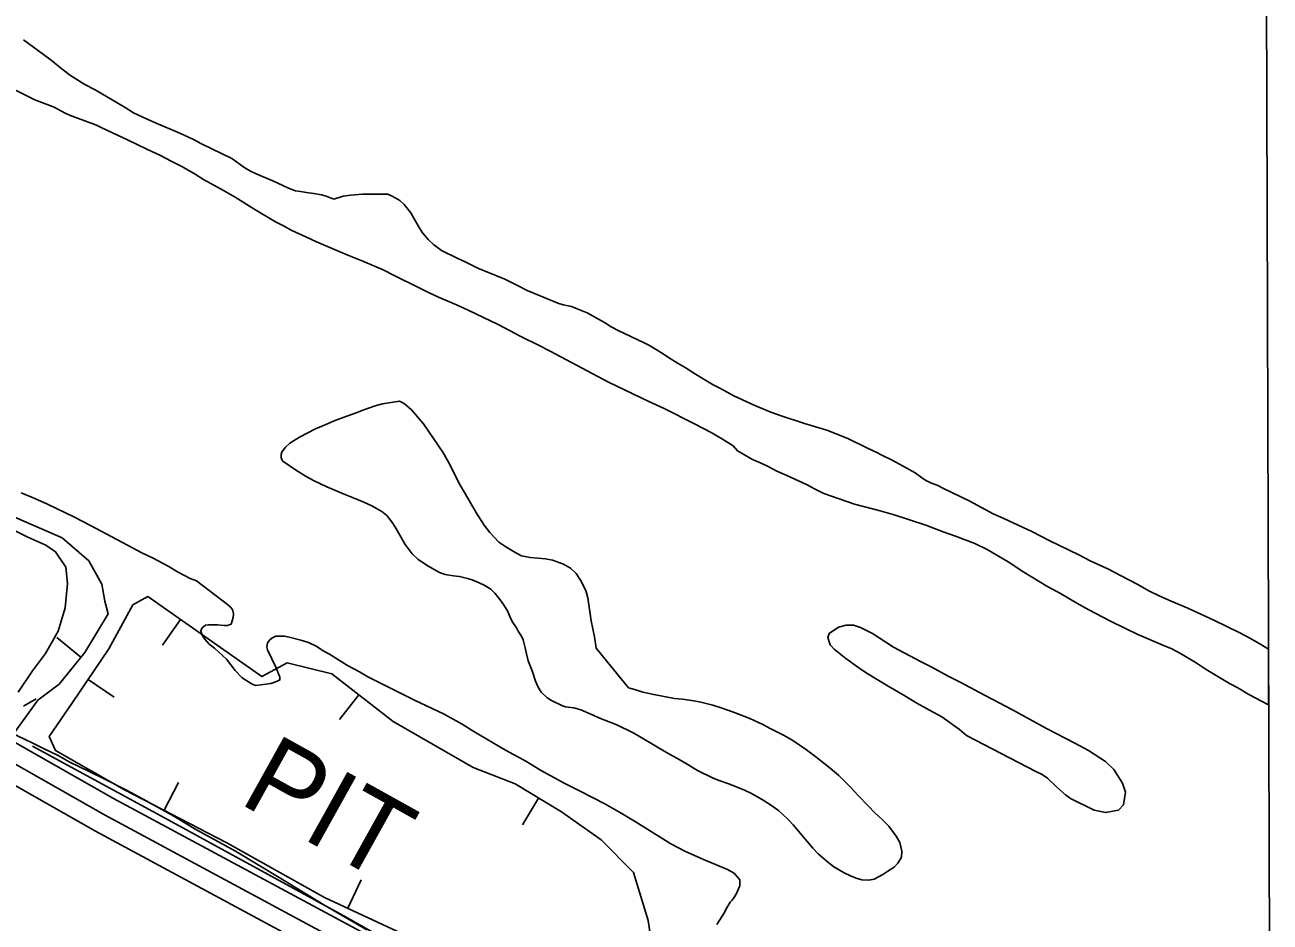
# Model space of a CAD drawing. Extents: x 3355724 to 3393621, y 594744 to 620174.
# Drawn here: x 3390457 to 3391453, y 600421 to 601139 of the extents above; entities that cross this region are included whole.
import ezdxf

# ---------------------------------------------------------------- set-up
doc = ezdxf.new("R2010")
doc.units = 0
for name, color, linetype in [('V-BORW-IDEN', 7, 'Continuous'), ('V-BORW-LINE', 7, 'Continuous'), ('V-GRID-FRAM', 7, 'Continuous'), ('V-ROAD-CNTR', 7, 'Continuous'), ('V-SITE-VEGE', 7, 'Continuous'), ('V-TOPO-SHOR', 7, 'Continuous')]:
    doc.layers.add(name, color=color, linetype=linetype)

msp = doc.modelspace()

# ---------------------------------------------------------------- linework, layer by layer
at = {"layer": 'V-BORW-LINE'}
for p, q in [((3390581.16, 600662.84), (3390566.81, 600642.36)), ((3390501.58, 600632.72), (3390482.21, 600648.53)), ((3390507.31, 600614.81), (3390528.02, 600600.81)), ((3390723.83, 600602.64), (3390708.48, 600582.91)), ((3390568.05, 600510.3), (3390579.58, 600532.48)), ((3390867.64, 600520.02), (3390854.68, 600498.64)), ((3390714.99, 600431.89), (3390725.56, 600454.54))]:
    msp.add_line(p, q, dxfattribs=at)
for points in [[(3390404.04, 600763.89), (3390486.52, 600728.08), (3390507.98, 600709.75), (3390518.18, 600691.2), (3390520.68, 600677.53), (3390523.21, 600667.3), (3390504.57, 600636.39), (3390484.04, 600611.21), (3390467.07, 600598.22), (3390447.03, 600570.55)], [(3390792.72, 600395.6), (3390696.46, 600440.54), (3390618.13, 600484.24), (3390536.51, 600526.7), (3390481.14, 600558.15), (3390476.13, 600569.17), (3390494.88, 600596.42), (3390523.86, 600639.31), (3390543.04, 600674.49), (3390554.93, 600681.22)], [(3390554.93, 600681.22), (3390646.3, 600617.19), (3390666.61, 600628.08), (3390702.33, 600619.37), (3390751.34, 600581.23), (3390815.26, 600544.46), (3390848.81, 600531.43), (3390885.84, 600508.99), (3390917.59, 600486.64), (3390943.54, 600460.38), (3390955.36, 600422.12), (3390964.29, 600360.67)], [(3390465.81, 600599.35), (3390455.56, 600593.54)]]:
    msp.add_lwpolyline(points, dxfattribs=at)
at = {"layer": 'V-GRID-FRAM'}
msp.add_lwpolyline([(3359807.56, 618312.07), (3391397.17, 618394.77), (3391452.71, 600211.22), (3359847.23, 600128.47), (3359807.56, 618312.07)], dxfattribs=at)
at = {"layer": 'V-ROAD-CNTR'}
for points in [[(3388228.72, 601693.23), (3388290.02, 601667.91), (3388382.76, 601630.25), (3388484.12, 601588.91), (3388574.06, 601563.02), (3388632.6, 601540.78), (3388725.29, 601494.91), (3388815.98, 601448.79), (3388916.72, 601401.26), (3389012.52, 601354.23), (3389189.03, 601262.02), (3389389.7, 601151.38), (3389619.09, 601026.75), (3389753.93, 600954.59), (3390006.73, 600812.22), (3390248.96, 600678.1), (3390527.61, 600519.78), (3390796.25, 600375.08), (3390931.22, 600305.52), (3391018, 600247.9), (3391053.94, 600226.08)], [(3388223, 601679.37), (3388284.34, 601654.03), (3388377.11, 601616.35), (3388479.2, 601574.72), (3388569.32, 601548.78), (3388626.59, 601527.02), (3388718.57, 601481.5), (3388809.38, 601435.32), (3388910.21, 601387.74), (3389005.74, 601340.84), (3389181.94, 601248.8), (3389382.49, 601138.23), (3389611.97, 601013.54), (3389746.71, 600941.44), (3389999.42, 600799.12), (3390241.62, 600665.02), (3390520.35, 600506.65), (3390789.26, 600361.81), (3390923.61, 600292.57), (3391009.95, 600235.24), (3391046.15, 600213.25)], [(3388217.27, 601665.5), (3388278.65, 601640.15), (3388371.45, 601602.46), (3388474.28, 601560.52), (3388564.57, 601534.53), (3388620.59, 601513.25), (3388711.84, 601468.09), (3388802.77, 601421.85), (3388903.71, 601374.22), (3388998.96, 601327.46), (3389174.84, 601235.59), (3389375.29, 601125.07), (3389604.85, 601000.34), (3389739.49, 600928.29), (3389992.1, 600786.03), (3390234.28, 600651.94), (3390513.08, 600493.52), (3390782.26, 600348.54), (3390916, 600279.61), (3391001.91, 600222.57), (3391038.36, 600200.43)]]:
    msp.add_lwpolyline(points, dxfattribs=at)
at = {"layer": 'V-SITE-VEGE'}
for p, q in [((3390455.7, 601126.52), (3390471.71, 601114.96)), ((3390471.71, 601114.96), (3390477.71, 601110.45)), ((3390477.71, 601110.45), (3390486.62, 601103.04)), ((3390486.62, 601103.04), (3390493.17, 601098.16)), ((3390464.75, 601078.65), (3390439.67, 601091.09)), ((3390493.17, 601098.16), (3390504.62, 601090.94)), ((3390504.62, 601090.94), (3390512.8, 601086.61)), ((3390512.8, 601086.61), (3390536.97, 601072.36)), ((3390480.01, 601072.72), (3390464.75, 601078.65)), ((3390488.37, 601068.21), (3390480.01, 601072.72)), ((3390536.97, 601072.36), (3390543.7, 601068.21)), ((3390492.36, 601066.41), (3390488.37, 601068.21)), ((3390504.53, 601061.73), (3390492.36, 601066.41)), ((3390513.98, 601058.31), (3390504.53, 601061.73)), ((3390543.7, 601068.21), (3390554.42, 601063.16)), ((3390554.42, 601063.16), (3390561.69, 601059.92)), ((3390561.69, 601059.92), (3390580.58, 601052)), ((3390518.71, 601055.97), (3390513.98, 601058.31)), ((3390538.87, 601046.6), (3390518.71, 601055.97)), ((3390580.58, 601052), (3390591.48, 601046.77)), ((3390554.86, 601038.85), (3390538.87, 601046.6)), ((3390591.48, 601046.77), (3390598.02, 601043.35)), ((3390598.02, 601043.35), (3390622.19, 601031.63)), ((3390564.67, 601034.35), (3390554.86, 601038.85)), ((3390573.58, 601029.66), (3390564.67, 601034.35)), ((3390582.12, 601025.33), (3390573.58, 601029.66)), ((3390622.19, 601031.63), (3390632.74, 601024.23)), ((3390592.84, 601019.02), (3390582.12, 601025.33)), ((3390632.74, 601024.23), (3390637.1, 601021.52)), ((3390637.1, 601021.52), (3390641.83, 601019.36)), ((3390641.83, 601019.36), (3390654.91, 601013.78)), ((3390599.57, 601014.87), (3390592.84, 601019.02)), ((3390615.56, 601006.03), (3390599.57, 601014.87)), ((3390654.91, 601013.78), (3390662.9, 601010.17)), ((3390662.9, 601010.17), (3390667.44, 601008.02)), ((3390625.02, 601000.62), (3390615.56, 601006.03)), ((3390640.65, 600990.87), (3390625.02, 601000.62)), ((3390667.44, 601008.02), (3390673.07, 601005.86)), ((3390673.07, 601005.86), (3390677.25, 601005.32)), ((3390677.25, 601005.32), (3390683.6, 601004.26)), ((3390683.6, 601004.26), (3390687.78, 601003.73)), ((3390687.78, 601003.73), (3390693.95, 601002.48)), ((3390693.95, 601002.48), (3390697.58, 601001.58)), ((3390697.58, 601001.58), (3390701.58, 600999.96)), ((3390701.58, 600999.96), (3390703.75, 600999.24)), ((3390703.75, 600999.24), (3390711.37, 601001.44)), ((3390711.37, 601001.44), (3390717.35, 601002.37)), ((3390717.35, 601002.37), (3390726.78, 601003.13)), ((3390726.78, 601003.13), (3390743.84, 601003.18)), ((3390743.84, 601003.18), (3390747.1, 601003.01)), ((3390747.1, 601003.01), (3390750.92, 601001.39)), ((3390750.92, 601001.39), (3390756.73, 600998.14)), ((3390657.19, 600980.95), (3390640.65, 600990.87)), ((3390756.73, 600998.14), (3390760.19, 600994.89)), ((3390760.19, 600994.89), (3390765.48, 600988.19)), ((3390663.55, 600977.7), (3390657.19, 600980.95)), ((3390765.48, 600988.19), (3390768.21, 600983.48)), ((3390768.21, 600983.48), (3390772.04, 600976.42)), ((3390670.27, 600974.1), (3390663.55, 600977.7)), ((3390681.54, 600969.05), (3390670.27, 600974.1)), ((3390772.04, 600976.42), (3390774.78, 600972.26)), ((3390774.78, 600972.26), (3390779.51, 600966.47)), ((3390690.08, 600965.09), (3390681.54, 600969.05)), ((3390704.43, 600958.79), (3390690.08, 600965.09)), ((3390779.51, 600966.47), (3390783.52, 600962.85)), ((3390783.52, 600962.85), (3390790.06, 600958.16)), ((3390715.15, 600954.28), (3390704.43, 600958.79)), ((3390726.96, 600949.61), (3390715.15, 600954.28)), ((3390743.31, 600942.58), (3390726.96, 600949.61)), ((3390790.06, 600958.16), (3390802.97, 600951.67)), ((3390802.97, 600951.67), (3390808.96, 600948.97)), ((3390752.21, 600938.08), (3390743.31, 600942.58)), ((3390808.96, 600948.97), (3390818.96, 600943.92)), ((3390818.96, 600943.92), (3390822.23, 600942.48)), ((3390822.23, 600942.48), (3390833.31, 600938.16)), ((3390754.76, 600936.63), (3390752.21, 600938.08)), ((3390768.93, 600929.79), (3390754.76, 600936.63)), ((3390779.47, 600924.56), (3390768.93, 600929.79)), ((3390833.31, 600938.16), (3390840.57, 600935.1)), ((3390840.57, 600935.1), (3390851.29, 600929.87)), ((3390851.29, 600929.87), (3390858.56, 600926.09)), ((3390787.65, 600920.78), (3390779.47, 600924.56)), ((3390801.82, 600914.65), (3390787.65, 600920.78)), ((3390858.56, 600926.09), (3390868.73, 600921.77)), ((3390868.73, 600921.77), (3390883.09, 600916.01)), ((3390811.26, 600910.33), (3390801.82, 600914.65)), ((3390835.25, 600898.98), (3390811.26, 600910.33)), ((3390883.09, 600916.01), (3390887.27, 600914.57)), ((3390887.27, 600914.57), (3390893.98, 600913.14)), ((3390893.98, 600913.14), (3390898.52, 600911.52)), ((3390898.52, 600911.52), (3390906.33, 600908.1)), ((3390906.33, 600908.1), (3390920.33, 600900.34)), ((3390920.33, 600900.34), (3390925.78, 600897.1)), ((3390848.88, 600891.59), (3390835.25, 600898.98)), ((3390853.42, 600889.24), (3390848.88, 600891.59)), ((3390925.78, 600897.1), (3390931.24, 600894.03)), ((3390931.24, 600894.03), (3390951.95, 600884.3)), ((3390867.41, 600882.39), (3390853.42, 600889.24)), ((3390876.86, 600877.53), (3390867.41, 600882.39)), ((3390951.95, 600884.3), (3390956.31, 600881.96)), ((3390956.31, 600881.96), (3390961.04, 600879.25)), ((3390923.57, 600852.82), (3390876.86, 600877.53)), ((3390961.04, 600879.25), (3390967.22, 600875.46)), ((3390967.22, 600875.46), (3390971.58, 600872.39)), ((3390971.58, 600872.39), (3390979.22, 600867.7)), ((3390979.22, 600867.7), (3390984.85, 600864.45)), ((3390984.85, 600864.45), (3390993.21, 600859.04)), ((3390955.91, 600837.14), (3390923.57, 600852.82)), ((3390993.21, 600859.04), (3391007.21, 600850.55)), ((3391007.21, 600850.55), (3391013.21, 600847.67)), ((3391013.21, 600847.67), (3391023.75, 600841.9)), ((3391023.75, 600841.9), (3391040.64, 600834.15)), ((3390968.09, 600831.56), (3390955.91, 600837.14)), ((3390992.25, 600819.3), (3390968.09, 600831.56)), ((3391040.64, 600834.15), (3391053.36, 600828.75)), ((3391053.36, 600828.75), (3391061.72, 600825.69)), ((3391061.72, 600825.69), (3391080.24, 600819.59)), ((3391005.52, 600812.45), (3390992.25, 600819.3)), ((3391014.79, 600807.22), (3391005.52, 600812.45)), ((3391080.24, 600819.59), (3391090.96, 600816.54)), ((3391090.96, 600816.54), (3391098.04, 600814.2)), ((3391098.04, 600814.2), (3391114.93, 600807.54)), ((3391023.15, 600801.8), (3391014.79, 600807.22)), ((3391026.79, 600797.82), (3391023.15, 600801.8)), ((3391114.93, 600807.54), (3391130.02, 600800.15)), ((3391030.43, 600795.66), (3391026.79, 600797.82)), ((3391038.79, 600790.97), (3391030.43, 600795.66)), ((3391045.51, 600787.91), (3391038.79, 600790.97)), ((3391130.02, 600800.15), (3391138.73, 600796.19)), ((3391138.73, 600796.19), (3391141.64, 600794.57)), ((3391141.64, 600794.57), (3391150.37, 600790.24)), ((3391150.37, 600790.24), (3391164, 600782.85)), ((3391051.14, 600785.2), (3391045.51, 600787.91)), ((3391058.23, 600781.6), (3391051.14, 600785.2)), ((3391066.05, 600777.99), (3391058.23, 600781.6)), ((3391164, 600782.85), (3391168.72, 600780.14)), ((3391081.85, 600770.97), (3391066.05, 600777.99)), ((3391088.39, 600767.36), (3391081.85, 600770.97)), ((3391168.72, 600780.14), (3391174, 600776.35)), ((3391174, 600776.35), (3391177.45, 600774.18)), ((3391177.45, 600774.18), (3391183.08, 600771.48)), ((3391183.08, 600771.48), (3391186.35, 600770.22)), ((3391095.84, 600763.76), (3391088.39, 600767.36)), ((3391108.01, 600759.26), (3391095.84, 600763.76)), ((3391186.35, 600770.22), (3391191.44, 600767.7)), ((3391191.44, 600767.7), (3391212.52, 600757.61)), ((3391120.37, 600755.13), (3391108.01, 600759.26)), ((3391140.88, 600749.75), (3391120.37, 600755.13)), ((3391212.52, 600757.61), (3391231.24, 600747.51)), ((3391151.96, 600746.71), (3391140.88, 600749.75)), ((3391177.38, 600738.44), (3391151.96, 600746.71)), ((3391231.24, 600747.51), (3391239.77, 600743.73)), ((3391239.77, 600743.73), (3391262.67, 600733.1)), ((3391191.19, 600733.05), (3391177.38, 600738.44)), ((3391201.18, 600729.45), (3391191.19, 600733.05)), ((3391262.67, 600733.1), (3391276.48, 600725.89)), ((3391216.62, 600723.69), (3391201.18, 600729.45)), ((3391226.43, 600718.83), (3391216.62, 600723.69)), ((3391276.48, 600725.89), (3391299.74, 600714.53)), ((3391243.16, 600709.09), (3391226.43, 600718.83)), ((3391299.74, 600714.53), (3391308.83, 600709.84)), ((3391255.7, 600700.6), (3391243.16, 600709.09)), ((3391274.24, 600689.59), (3391255.7, 600700.6)), ((3391308.83, 600709.84), (3391323.36, 600702.99)), ((3391323.36, 600702.99), (3391332.99, 600698.13)), ((3391332.99, 600698.13), (3391346.99, 600690.74)), ((3391346.99, 600690.74), (3391355.71, 600685.87)), ((3391284.96, 600683.64), (3391274.24, 600689.59)), ((3391298.05, 600675.88), (3391284.96, 600683.64)), ((3391355.71, 600685.87), (3391364.61, 600681.54)), ((3391364.61, 600681.54), (3391373.7, 600677.4)), ((3391307.69, 600670.47), (3391298.05, 600675.88)), ((3391373.7, 600677.4), (3391386.78, 600671.82)), ((3391386.78, 600671.82), (3391407.67, 600662.45)), ((3391324.58, 600661.82), (3391307.69, 600670.47)), ((3391337.67, 600655.51), (3391324.58, 600661.82)), ((3391407.67, 600662.45), (3391428.39, 600652.18)), ((3391346.39, 600651.18), (3391337.67, 600655.51)), ((3391366.92, 600642.36), (3391346.39, 600651.18)), ((3391428.39, 600652.18), (3391436.39, 600647.85)), ((3391374.18, 600639.48), (3391366.92, 600642.36)), ((3391436.39, 600647.85), (3391444.38, 600643.34)), ((3391444.38, 600643.34), (3391451.4, 600639.22)), ((3391381.09, 600635.69), (3391374.18, 600639.48)), ((3391393.45, 600628.3), (3391381.09, 600635.69)), ((3391451.4, 600639.22), (3391451.54, 600594.51)), ((3391401.63, 600622.88), (3391393.45, 600628.3)), ((3391420.17, 600611.69), (3391401.63, 600622.88)), ((3391426.9, 600608.08), (3391420.17, 600611.69)), ((3391435.8, 600602.85), (3391426.9, 600608.08)), ((3391451.54, 600594.51), (3391435.8, 600602.85))]:
    msp.add_line(p, q, dxfattribs=at)
for points in [[(3390986.43, 600547.15), (3390980.06, 600550.94), (3390969.89, 600556.35), (3390951.53, 600567.36), (3390943.71, 600571.87), (3390930.08, 600578.53), (3390915.73, 600584.11), (3390911.19, 600586.28), (3390901.38, 600590.6), (3390895.75, 600592.21), (3390889.21, 600593.1), (3390886.67, 600593.82), (3390877.95, 600598.14), (3390874.32, 600600.49), (3390869.77, 600604.83), (3390867.21, 600608.81), (3390865.02, 600613.52), (3390862.45, 600621.86), (3390859.35, 600629.83), (3390858.06, 600635.27), (3390856.77, 600640.16), (3390855.3, 600646.51), (3390854.02, 600649.41), (3390851.28, 600653.39), (3390849.82, 600656.29), (3390846.54, 600661.36), (3390844.71, 600665.16), (3390842.89, 600669.33), (3390839.42, 600674.76), (3390836.87, 600678.56), (3390832.5, 600683.99), (3390829.41, 600687.06), (3390824.13, 600690.31), (3390820.13, 600692.29), (3390814.5, 600694.63), (3390810.69, 600695.71), (3390804.34, 600697.14), (3390799.62, 600697.67), (3390792.9, 600698.92), (3390788.36, 600700.53), (3390778.54, 600706.13), (3390771.09, 600711.18), (3390766.54, 600715.34), (3390760.89, 600722.94), (3390753.41, 600735.98), (3390750.68, 600740.14), (3390746.3, 600745.94), (3390742.3, 600749.37), (3390734.12, 600753.7), (3390727.95, 600756.76), (3390718.68, 600760.54), (3390711.96, 600763.06), (3390705.24, 600765.94), (3390698.33, 600769), (3390687.98, 600773.87), (3390681.62, 600777.3), (3390673.07, 600782.53), (3390663.07, 600789.57), (3390661.61, 600791.92), (3390661.6, 600794.83), (3390662.32, 600796.82), (3390665.21, 600800.82), (3390668.65, 600803.92), (3390676.43, 600808.84), (3390689.11, 600815.41), (3390695.63, 600817.98), (3390705.42, 600822.36), (3390721.73, 600828.22), (3390727.89, 600830.6), (3390736.95, 600833.71), (3390742.75, 600835.36), (3390751.27, 600836.84), (3390756.35, 600837.4), (3390759.98, 600835.6), (3390765.99, 600830.54), (3390775.46, 600819.32), (3390790.95, 600796.7), (3390796.61, 600786.74), (3390804.09, 600771.7), (3390809.02, 600763.01), (3390816.13, 600751.24), (3390817.96, 600747.8), (3390823.98, 600738.39), (3390828.53, 600732.42), (3390835.81, 600724.82), (3390841.27, 600721.03), (3390849.45, 600716.15), (3390853.99, 600713.81), (3390860.89, 600712.38), (3390873.05, 600711.51), (3390878.68, 600710.26), (3390887.58, 600707.03), (3390893.03, 600703.96), (3390897.76, 600699.62), (3390901.23, 600694.19), (3390905.42, 600686.04), (3390907.08, 600680.06), (3390909.68, 600661.92), (3390912.25, 600648.87), (3390913.56, 600639.8), (3390939.42, 600608.14)], [(3390453.62, 600764.3), (3390464.7, 600759.61), (3390474.88, 600755.11), (3390496.32, 600744.66), (3390509.22, 600738.17), (3390530.31, 600726.81), (3390550.84, 600715.99), (3390559.2, 600712.03), (3390571.37, 600705.54), (3390578.83, 600701.02), (3390588.82, 600695.61), (3390593.91, 600693.82)], [(3390593.91, 600693.82), (3390618.64, 600674.85), (3390620.83, 600672.86), (3390622.65, 600670.87), (3390623.56, 600667.42), (3390623.4, 600664.34), (3390621.6, 600659.25), (3390618.7, 600657.97), (3390615.98, 600657.97), (3390611.08, 600658.49), (3390607.99, 600658.67), (3390603.64, 600658.65), (3390601.1, 600658.28), (3390598.21, 600655.91), (3390597.49, 600653.55), (3390598.77, 600649.74), (3390600.59, 600647.21), (3390604.23, 600643.05), (3390608.42, 600639.8), (3390617.88, 600631.12), (3390624.98, 600622.08), (3390630.44, 600616.29), (3390638.44, 600611.05), (3390641.35, 600610.15), (3390653.32, 600611.64), (3390657.85, 600613.29), (3390660.75, 600614.57), (3390660.56, 600616.75), (3390657.63, 600624.17), (3390650.87, 600638.67), (3390650.32, 600640.66), (3390650.67, 600644.29), (3390652.66, 600646.47), (3390654.29, 600647.93), (3390657.37, 600649.39), (3390659.54, 600649.58), (3390664.26, 600649.41), (3390668.08, 600648.7), (3390677.52, 600646.37), (3390683.69, 600644.4), (3390690.23, 600641.33), (3390695.32, 600637.9), (3390700.41, 600635.2), (3390714.77, 600626.18), (3390724.4, 600620.94), (3390730.95, 600616.97), (3390764.02, 600600.39), (3390768.38, 600598.41), (3390792, 600587.06), (3390806.36, 600579.12), (3390815.81, 600573.17), (3390841.08, 600558.37), (3390857.44, 600549.54), (3390869.25, 600542.32), (3390888.15, 600531.85), (3390900.87, 600525.55), (3390920.68, 600515.27), (3390933.59, 600507.87), (3390945.59, 600500.83), (3390973.4, 600483.33), (3390984.48, 600477.56), (3390999.38, 600470.9), (3391018.82, 600462.79), (3391024.09, 600459.91), (3391028.46, 600454.66), (3391028.48, 600449.76), (3391025.6, 600443.04), (3391023.79, 600440.13), (3391022.35, 600438.31), (3391020.72, 600436.68), (3391017.47, 600430.86), (3391016.21, 600428.32), (3391010.07, 600418.86)], [(3390939.42, 600608.14), (3390945.41, 600606.52), (3390950.86, 600604.73), (3390959.76, 600602.76), (3390976.28, 600599.73), (3390982.63, 600599.03), (3390991.7, 600597.79), (3390997.33, 600596.71), (3391006.95, 600594.39), (3391013.67, 600592.23), (3391023.48, 600588.82), (3391036.56, 600583.6), (3391046.92, 600578.73), (3391053.46, 600575.31), (3391064, 600570.08), (3391071.09, 600566.11), (3391082, 600558.53), (3391089.45, 600552.93), (3391100.91, 600543.9), (3391107.83, 600538.11), (3391117.29, 600528.53), (3391122.94, 600522.2), (3391131.31, 600513.7), (3391136.59, 600508.09), (3391142.23, 600503.03), (3391147.69, 600497.6), (3391153.7, 600489.46), (3391156.44, 600484.39), (3391158.09, 600477.5), (3391157.75, 600472.78), (3391155.04, 600467.87), (3391151.96, 600464.78), (3391147.08, 600461.5), (3391142.91, 600458.94), (3391136.03, 600455.11), (3391131.86, 600454.19), (3391126.06, 600454.53), (3391121.7, 600455.79), (3391116.98, 600457.77), (3391111.89, 600460.3), (3391103.71, 600464.98), (3391098.62, 600468.96), (3391091.34, 600475.47), (3391086.97, 600479.81), (3391071.31, 600498.62), (3391066.57, 600503.33), (3391059.66, 600509.65), (3391054.75, 600513.45), (3391047.11, 600518.32), (3391042.21, 600521.21), (3391037.3, 600523.91), (3391032.39, 600526.26), (3391019.86, 600531.3), (3391012.05, 600533.99), (3391007.14, 600535.97), (3390994.6, 600542.1), (3390986.43, 600547.15)], [(3390659.99, 600456.55), (3390625.09, 600477.48), (3390605.82, 600488.3), (3390593.46, 600494.98), (3390575.83, 600505.44), (3390551.29, 600519.15), (3390537.85, 600526.36), (3390519.68, 600535.74), (3390508.05, 600541.14), (3390492.06, 600549.07), (3390483.33, 600553.94), (3390472.61, 600559.17), (3390467.34, 600561.88), (3390462.44, 600564.22), (3390456.8, 600566.74), (3390437.36, 600576.11)], [(3390730.15, 600414.69), (3390695.8, 600434.71), (3390659.99, 600456.55)]]:
    msp.add_lwpolyline(points, dxfattribs=at)
msp.add_lwpolyline([(3391209.87, 600570.09), (3391204.23, 600574.79), (3391190.23, 600584.9), (3391180.23, 600590.31), (3391170.24, 600595.9), (3391160.42, 600601.86), (3391147.15, 600609.44), (3391139.7, 600614.13), (3391129.52, 600620.08), (3391123.88, 600624.24), (3391113.34, 600631.64), (3391104.06, 600639.05), (3391100.78, 600642.67), (3391098.95, 600648.46), (3391100.03, 600651.55), (3391107.45, 600656.84), (3391113.61, 600658.31), (3391119.42, 600658.33), (3391125.05, 600656.53), (3391134.68, 600651.67), (3391151.59, 600640.84), (3391173.21, 600629.29), (3391181.57, 600624.97), (3391195.2, 600617.57), (3391205.38, 600612.53), (3391219.74, 600604.77), (3391246.63, 600590.53), (3391273.89, 600575.74), (3391296.61, 600564.02), (3391307.33, 600558.07), (3391320.97, 600549.22), (3391327.7, 600542.9), (3391334.63, 600532.03), (3391337.01, 600524.6), (3391335.41, 600514.62), (3391331.44, 600510.25), (3391320.92, 600508.41), (3391312.02, 600510.19), (3391293.13, 600519.56), (3391288.94, 600522.63), (3391282.03, 600528.6), (3391274.57, 600536.01), (3391270.39, 600538.72), (3391265.3, 600541.24)], close=True, dxfattribs=at)
at = {"layer": 'V-TOPO-SHOR'}
for points in [[(3390415.65, 600750.49), (3390459.09, 600728.6), (3390473.57, 600722.45), (3390481.17, 600716.97), (3390489.47, 600704.6), (3390490.89, 600691.53), (3390488.88, 600672.24), (3390483.44, 600653.63), (3390473.17, 600635.7), (3390462.89, 600621.89), (3390451.24, 600604.64)], [(3390462.91, 600561.61), (3390568.44, 600504.12), (3390711.22, 600426.09), (3390850.56, 600347.37), (3390955.4, 600290.56)]]:
    msp.add_lwpolyline(points, dxfattribs=at)

# ---------------------------------------------------------------- texts
at = {"layer": 'V-BORW-IDEN'}
msp.add_text('PIT', height=64, rotation=330.93308, dxfattribs=at).set_placement((3390626.73, 600516.54))

doc.saveas('drawing.dxf')
